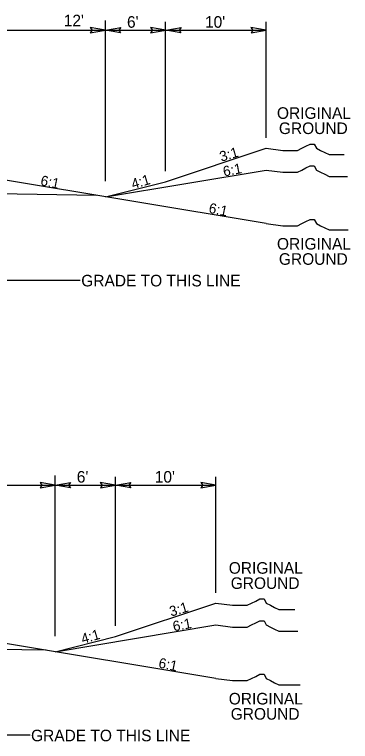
# Model space of a CAD drawing. Extents: x 2176156 to 2177167, y 76401 to 76644.
# Drawn here: x 2177033.9 to 2177067.3, y 76544 to 76616.3 of the extents above; entities that cross this region are included whole.
import ezdxf

# ---------------------------------------------------------------- set-up
doc = ezdxf.new("R2010")
doc.units = 0
for name, color, linetype in [('Exist Building', 7, 'Continuous'), ('Exist Roads Curbs', 7, 'Continuous'), ('Exist Roads EOP Other', 7, 'Continuous'), ('Exist Roads Soil', 7, 'Continuous'), ('Exist Structure Minor Culvert Topo', 7, 'Continuous'), ('Old_Level_1', 7, 'Continuous'), ('Old_Level_3', 7, 'Continuous')]:
    doc.layers.add(name, color=color, linetype=linetype)

msp = doc.modelspace()

# ---------------------------------------------------------------- linework, layer by layer
at = {"layer": 'Exist Building'}
for p, q in [((2177042.063, 76598.356), (2177020.947, 76598.67)), ((2177037.063, 76553.101), (2177015.947, 76553.415))]:
    msp.add_line(p, q, dxfattribs=at)
at = {"layer": 'Exist Roads Curbs'}
for points in [[(2177058.947, 76603.042), (2177060.617, 76602.834), (2177061.035, 76602.834), (2177061.662, 76602.834), (2177062.08, 76602.834), (2177062.498, 76603.042), (2177062.915, 76603.252), (2177063.333, 76603.461), (2177063.751, 76603.461), (2177063.96, 76603.042), (2177064.378, 76602.834), (2177064.796, 76602.624), (2177065.213, 76602.416), (2177065.631, 76602.416), (2177066.049, 76602.416), (2177066.466, 76602.416), (2177066.738, 76602.416)], [(2177058.947, 76600.875), (2177060.618, 76600.667), (2177061.035, 76600.667), (2177061.663, 76600.667), (2177062.08, 76600.667), (2177062.498, 76600.875), (2177062.916, 76601.085), (2177063.333, 76601.295), (2177063.751, 76601.295), (2177063.961, 76600.875), (2177064.378, 76600.667), (2177064.796, 76600.458), (2177065.214, 76600.25), (2177065.631, 76600.25), (2177066.049, 76600.25), (2177066.467, 76600.25), (2177066.884, 76600.25), (2177067.047, 76600.25)], [(2177058.947, 76595.542), (2177060.617, 76595.334), (2177061.035, 76595.334), (2177061.662, 76595.334), (2177062.08, 76595.334), (2177062.498, 76595.542), (2177062.915, 76595.752), (2177063.333, 76595.961), (2177063.751, 76595.961), (2177063.96, 76595.542), (2177064.378, 76595.334), (2177064.796, 76595.124), (2177065.213, 76594.916), (2177065.631, 76594.916), (2177066.049, 76594.916), (2177066.466, 76594.916), (2177066.884, 76594.916), (2177067.125, 76594.916)], [(2177053.947, 76557.787), (2177055.617, 76557.579), (2177056.035, 76557.579), (2177056.662, 76557.579), (2177057.08, 76557.579), (2177057.498, 76557.787), (2177057.915, 76557.996), (2177058.333, 76558.206), (2177058.751, 76558.206), (2177058.96, 76557.787), (2177059.378, 76557.579), (2177059.796, 76557.369), (2177060.213, 76557.161), (2177060.631, 76557.161), (2177061.049, 76557.161), (2177061.466, 76557.161), (2177061.806, 76557.161)], [(2177053.947, 76555.62), (2177055.618, 76555.412), (2177056.035, 76555.412), (2177056.663, 76555.412), (2177057.08, 76555.412), (2177057.498, 76555.62), (2177057.916, 76555.83), (2177058.333, 76556.039), (2177058.751, 76556.039), (2177058.961, 76555.62), (2177059.378, 76555.412), (2177059.796, 76555.202), (2177060.214, 76554.994), (2177060.631, 76554.994), (2177061.049, 76554.994), (2177061.467, 76554.994), (2177061.884, 76554.994), (2177062.116, 76554.994)], [(2177053.947, 76550.287), (2177055.617, 76550.079), (2177056.035, 76550.079), (2177056.662, 76550.079), (2177057.08, 76550.079), (2177057.498, 76550.287), (2177057.915, 76550.496), (2177058.333, 76550.706), (2177058.751, 76550.706), (2177058.96, 76550.287), (2177059.378, 76550.079), (2177059.796, 76549.869), (2177060.213, 76549.661), (2177060.631, 76549.661), (2177061.049, 76549.661), (2177061.466, 76549.661), (2177061.884, 76549.661), (2177062.302, 76549.661), (2177062.348, 76549.661)]]:
    msp.add_lwpolyline(points, dxfattribs=at)
at = {"layer": 'Exist Roads EOP Other'}
for p, q in [((2177048.947, 76599.709), (2177058.947, 76603.042)), ((2177042.947, 76598.209), (2177048.947, 76599.709)), ((2177043.947, 76554.453), (2177053.947, 76557.787)), ((2177037.947, 76552.953), (2177043.947, 76554.453))]:
    msp.add_line(p, q, dxfattribs=at)
at = {"layer": 'Exist Roads Soil'}
for p, q in [((2177058.947, 76595.542), (2177030.995, 76600.201)), ((2177042.947, 76598.209), (2177058.947, 76600.875)), ((2177037.947, 76552.953), (2177053.947, 76555.62)), ((2177053.947, 76550.287), (2177025.995, 76554.945))]:
    msp.add_line(p, q, dxfattribs=at)
at = {"layer": 'Old_Level_1'}
for points in [[(2177041.45, 76614.521), (2177042.96, 76614.781), (2177041.442, 76615.049), (2177041.635, 76614.781)], [(2177044.469, 76614.521), (2177042.96, 76614.781), (2177044.478, 76615.049), (2177044.285, 76614.781)], [(2177047.45, 76614.521), (2177048.96, 76614.781), (2177047.442, 76615.049), (2177047.635, 76614.781)], [(2177050.469, 76614.521), (2177048.96, 76614.781), (2177050.478, 76615.049), (2177050.285, 76614.781)], [(2177057.45, 76614.521), (2177058.96, 76614.781), (2177057.442, 76615.049), (2177057.635, 76614.781)], [(2177036.45, 76569.266), (2177037.96, 76569.526), (2177036.442, 76569.794), (2177036.635, 76569.526)], [(2177039.469, 76569.266), (2177037.96, 76569.526), (2177039.478, 76569.794), (2177039.285, 76569.526)], [(2177042.45, 76569.266), (2177043.96, 76569.526), (2177042.442, 76569.794), (2177042.635, 76569.526)], [(2177045.469, 76569.266), (2177043.96, 76569.526), (2177045.478, 76569.794), (2177045.285, 76569.526)], [(2177052.45, 76569.266), (2177053.96, 76569.526), (2177052.442, 76569.794), (2177052.635, 76569.526)]]:
    msp.add_lwpolyline(points, close=True, dxfattribs=at)
at = {"layer": 'Old_Level_3'}
for p, q in [((2177042.947, 76599.754), (2177042.947, 76615.747)), ((2177048.947, 76600.771), (2177048.947, 76615.613)), ((2177058.947, 76604.073), (2177058.947, 76615.613)), ((2177030.96, 76614.781), (2177042.96, 76614.781)), ((2177042.96, 76614.781), (2177048.96, 76614.781)), ((2177048.96, 76614.781), (2177058.96, 76614.781)), ((2177040.448, 76589.902), (2177030.88, 76589.902)), ((2177037.947, 76554.498), (2177037.947, 76570.491)), ((2177043.947, 76555.516), (2177043.947, 76570.358)), ((2177053.947, 76558.818), (2177053.947, 76570.358)), ((2177025.96, 76569.526), (2177037.96, 76569.526)), ((2177037.96, 76569.526), (2177043.96, 76569.526)), ((2177043.96, 76569.526), (2177053.96, 76569.526)), ((2177035.448, 76544.647), (2177025.88, 76544.647))]:
    msp.add_line(p, q, dxfattribs=at)

# ---------------------------------------------------------------- texts
at = {"layer": 'Exist Roads Curbs'}
for s, rotation, p in [('3:1', 16.46494, (2177054.493, 76601.697)), ('6:1', 10.81682, (2177054.761, 76600.228)), ('6:1', 348.51345, (2177036.429, 76599.377)), ('4:1', 16.46494, (2177045.703, 76598.976)), ('6:1', 348.51345, (2177053.179, 76596.636)), ('3:1', 16.46494, (2177049.493, 76556.441)), ('6:1', 10.81682, (2177049.761, 76554.973)), ('4:1', 16.46494, (2177040.703, 76553.721)), ('6:1', 348.51345, (2177048.179, 76551.381))]:
    msp.add_text(s, height=1.0064, rotation=rotation, dxfattribs=at).set_placement(p)
at = {"layer": 'Exist Structure Minor Culvert Topo'}
for s, height, p in [("12' ", 1.1533, (2177038.805, 76615.176)), ("6'", 1.1533, (2177045.102, 76615.033)), ("10'", 1.1533, (2177052.867, 76615.033)), ('ORIGINAL', 1.1533, (2177060.03, 76605.968)), ('GROUND', 1.1533, (2177060.224, 76604.456)), ('ORIGINAL', 1.1533, (2177060.03, 76592.96)), ('GROUND', 1.1533, (2177060.224, 76591.448)), ('GRADE TO THIS LINE', 1.15334, (2177040.548, 76589.298)), ("6'", 1.1533, (2177040.102, 76569.778)), ("10'", 1.1533, (2177047.867, 76569.778)), ('ORIGINAL', 1.1533, (2177055.234, 76560.713)), ('GROUND', 1.1533, (2177055.428, 76559.201)), ('ORIGINAL', 1.1533, (2177055.234, 76547.705)), ('GROUND', 1.1533, (2177055.428, 76546.193)), ('GRADE TO THIS LINE', 1.15334, (2177035.548, 76544.042))]:
    msp.add_text(s, height=height, dxfattribs=at).set_placement(p)

doc.saveas('drawing.dxf')
